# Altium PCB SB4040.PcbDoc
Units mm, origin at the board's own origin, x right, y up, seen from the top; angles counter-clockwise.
Board outline 40 x 40 mm, 2 copper layers (Top Layer, Bottom Layer); 0 components, 0 nets, 4 pads, 0 vias.
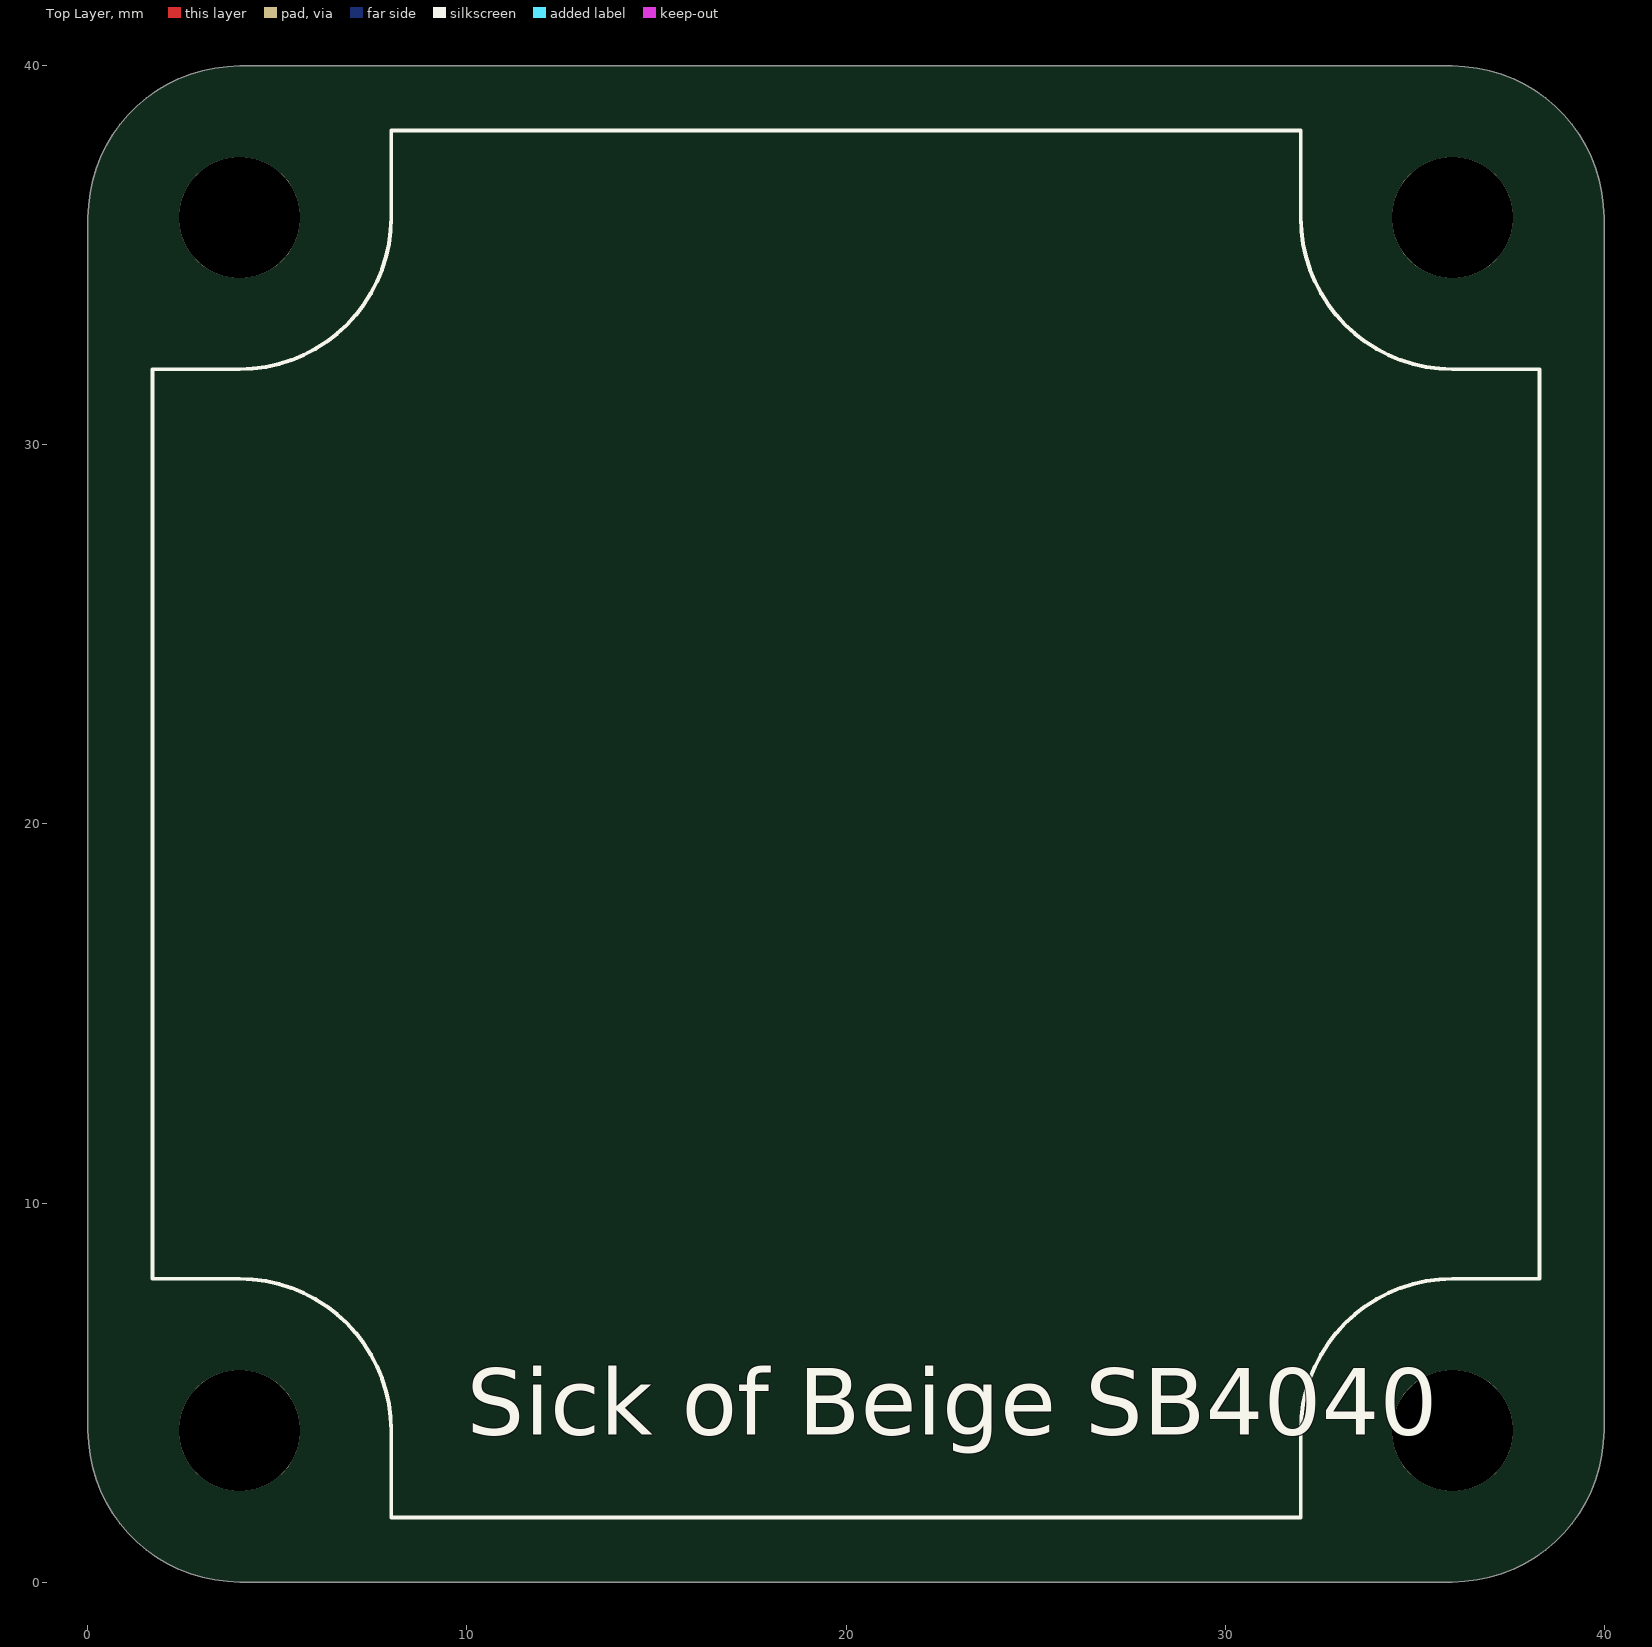
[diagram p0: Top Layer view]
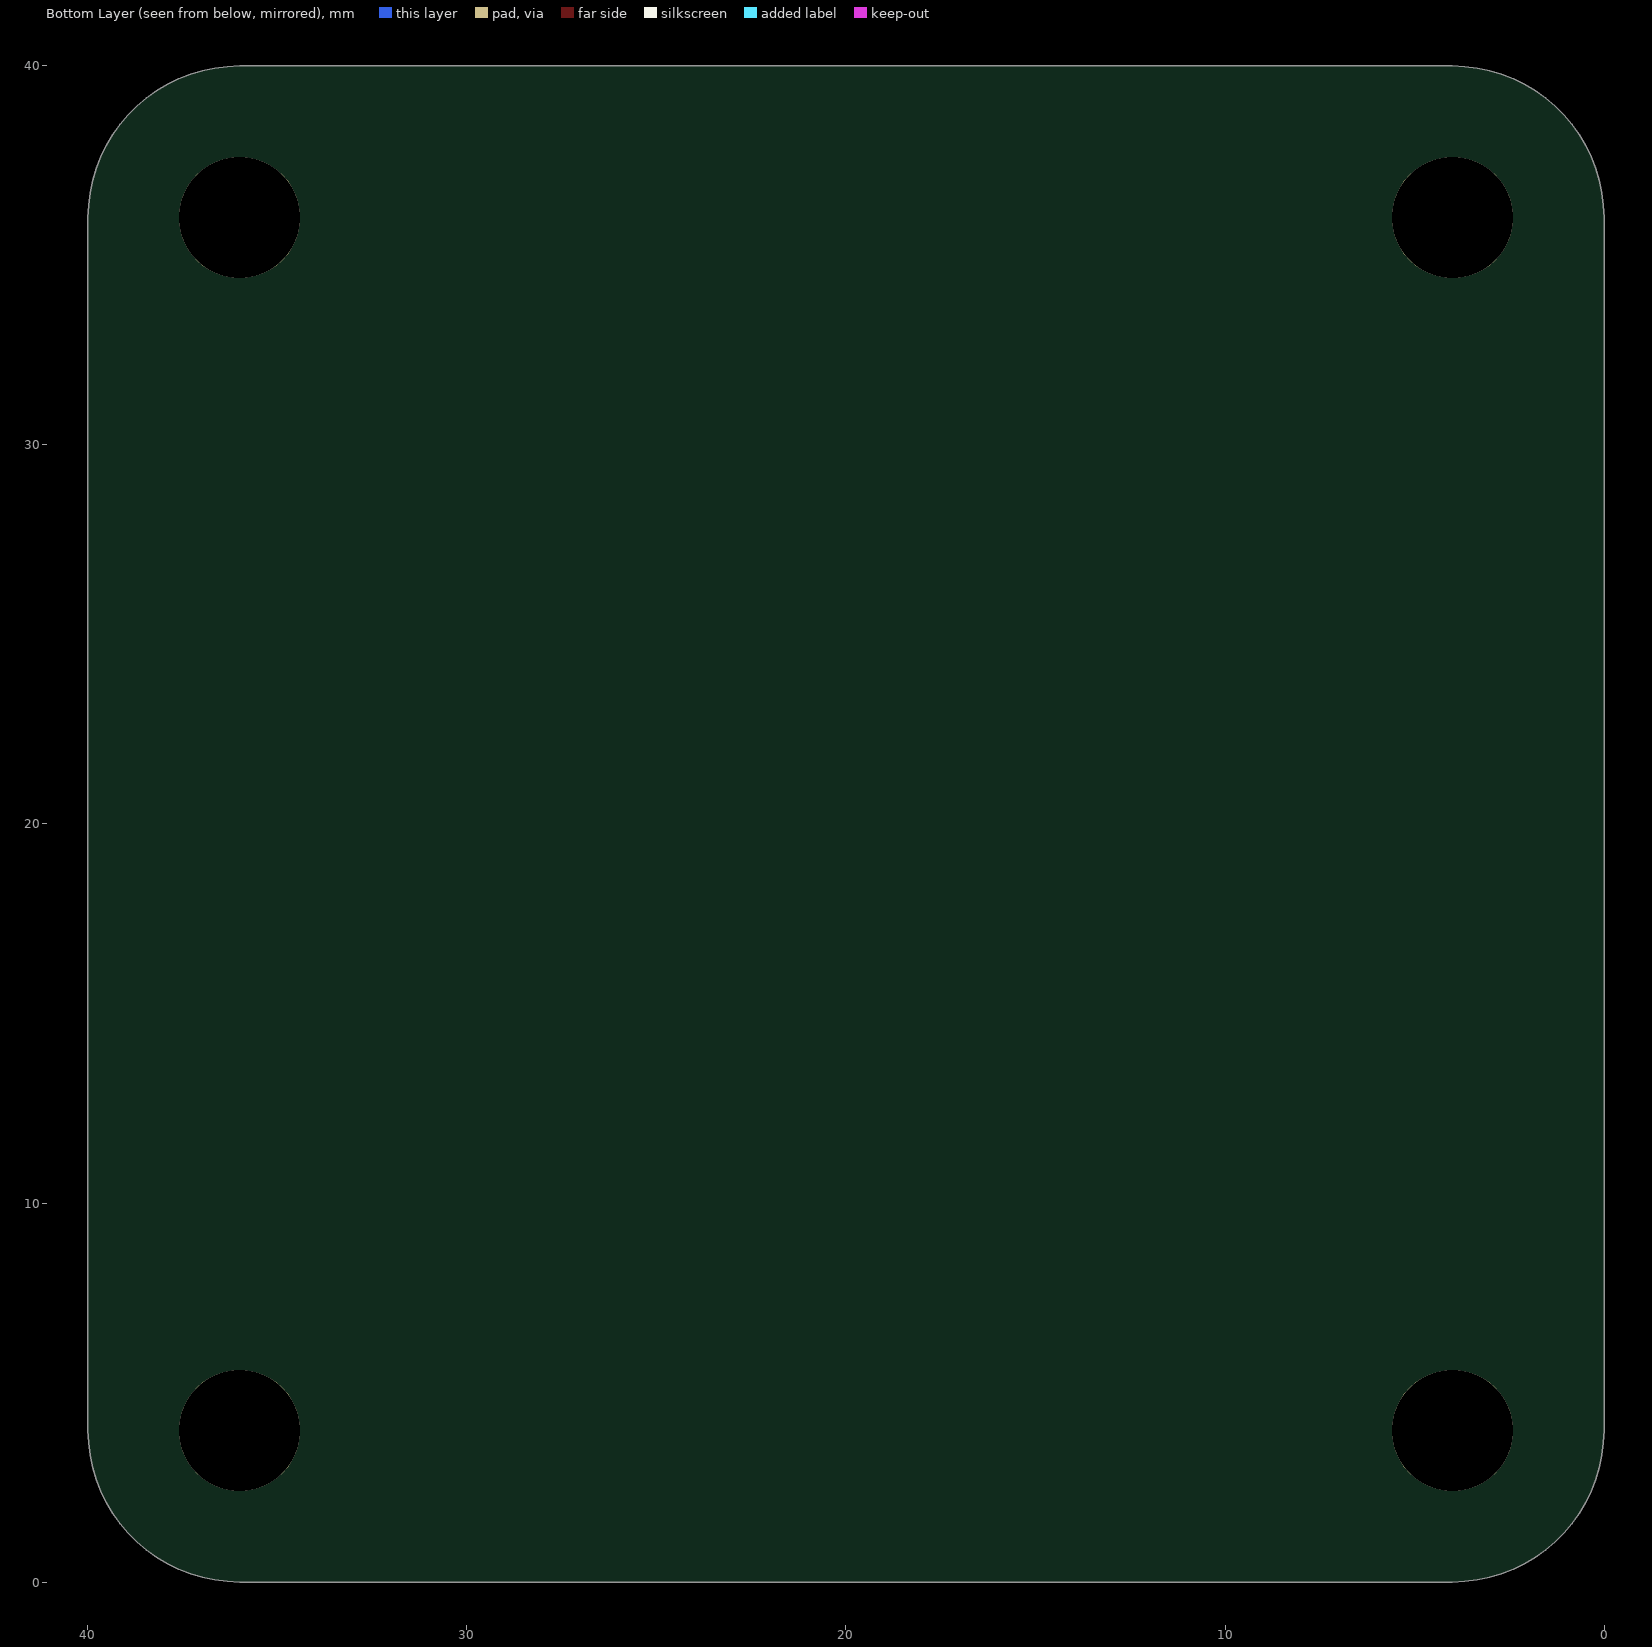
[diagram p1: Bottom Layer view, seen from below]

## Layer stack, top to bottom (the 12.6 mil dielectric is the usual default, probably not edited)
Top Layer: signal copper 0.0356
Dielectric: dielectric 0.32, FR-4, Dk 4.8
Bottom Layer: signal copper 0.0356

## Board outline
4,0 cw(c4,4) 0,4 0,36 cw(c4,36) 4,40 36,40 cw(c36,36) 40,36 40,4 cw(c36,4) 36,0

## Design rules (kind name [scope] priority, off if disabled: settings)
Clearance [All] p1: gap=0.254
PolygonConnect [All] p1: connectstyle=Relief reliefconductorwidth=0.254 reliefentries=4 polygonreliefangle="90 Angle" airgapwidth=0.254
RoutingVias [All] p1: holewidth=0.711 width=1.27 viastyle="Through Hole" minholewidth=0.711 minwidth=1.27 maxholewidth=0.711 maxwidth=1.27
SolderMaskExpansion [All] p1: expansion=0.102
Width [All] p1: maxlimit=0.254 minlimit=0.254 preferedwidth=0.254
28 further rules are at their usual default settings.

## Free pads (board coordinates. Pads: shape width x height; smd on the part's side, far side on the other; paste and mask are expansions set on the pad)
  round 3.2 hole 3.2 unplated: 0(4,4) 1(4,36) 2(36,36) 3(36,4)

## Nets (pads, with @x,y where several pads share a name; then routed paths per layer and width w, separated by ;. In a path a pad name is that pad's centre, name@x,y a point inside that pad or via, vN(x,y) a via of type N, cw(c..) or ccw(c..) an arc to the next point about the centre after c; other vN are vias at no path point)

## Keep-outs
Top Overlay:
  lines w0.102: 1.7,8 4,8 cw(c4,4) 8,4 8,1.7 32,1.7 32,4 cw(c36,4) 36,8 38.3,8 38.3,32 36,32 cw(c36,36) 32,36 32,38.3 8,38.3 8,36 cw(c4,36) 4,32 1.7,32 1.7,8

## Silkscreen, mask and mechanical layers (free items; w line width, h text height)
Top Overlay:
  text "Sick of Beige SB4040" at 10,3.3 h3
Mechanical 1:
  the board outline again, w0.102
Mechanical 4:
  circle w0.102: c36,36 r1.6
  circle w0.102: c4,36 r1.6
  circle w0.102: c4,4 r1.6
  circle w0.102: c36,4 r1.6
  lines w0.102: 0,20 40,20 ; 20,0 20,40

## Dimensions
36,40 to 36,0 on Mechanical 3
0,4 to 40,4 on Mechanical 3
